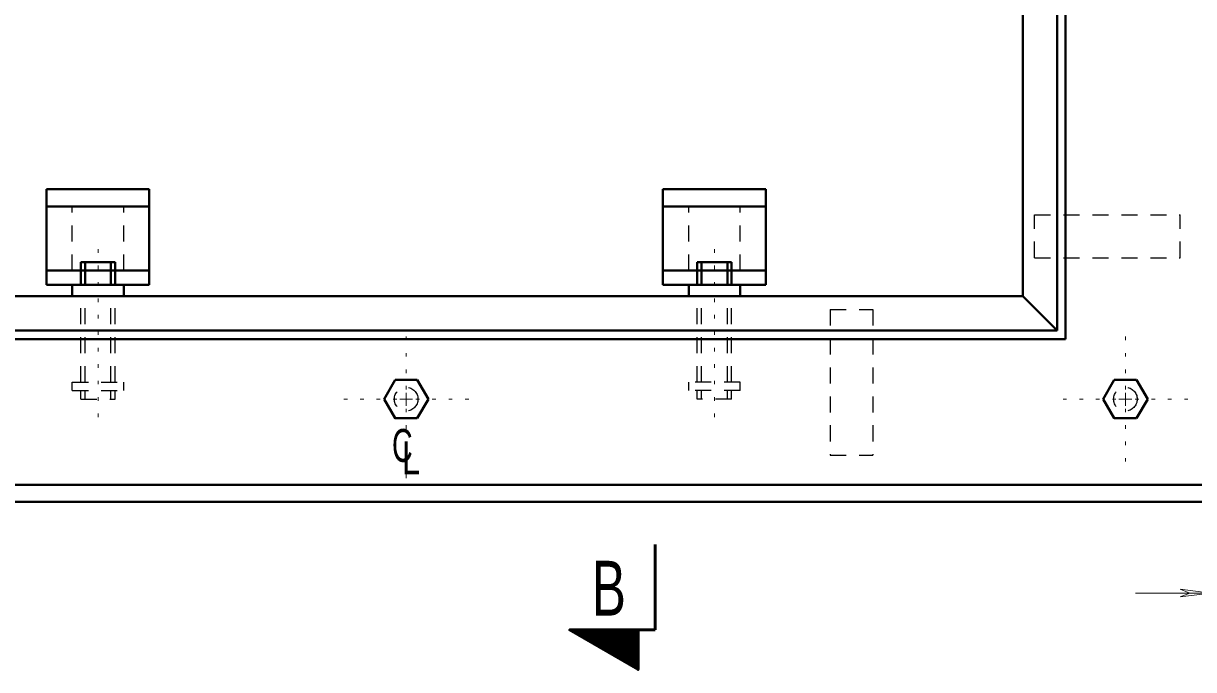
# Model space of a CAD drawing. Extents: x 312583 to 312853, y 144419 to 144586.
# Drawn here: x 312733.29 to 312766.04, y 144537.22 to 144555.29 of the extents above; entities that cross this region are included whole.
import ezdxf
from ezdxf.enums import TextEntityAlignment as Align

# ---------------------------------------------------------------- set-up
doc = ezdxf.new("R2010")
doc.units = 0
doc.header["$LTSCALE"] = 0.3
doc.linetypes.add('DOTTED', pattern=[1.5, 0.3, -1.2])
doc.linetypes.add('SHORT_DASHED', pattern=[2.7, 1.5, -1.2])
doc.layers.add('1', color=7, linetype='Continuous', lineweight=40)
doc.layers.add('2', color=7, linetype='Continuous', lineweight=13)

msp = doc.modelspace()

# ---------------------------------------------------------------- linework, layer by layer
at = {"layer": '1'}
for p, q in [((312761.2554, 144556.2456), (312761.2554, 144547.6589)), ((312733.939, 144550.6566), (312736.814, 144550.6566)), ((312733.939, 144547.9809), (312733.939, 144550.6566)), ((312736.814, 144547.9809), (312736.814, 144550.6566)), ((312754.064, 144550.6566), (312751.189, 144550.6566)), ((312751.189, 144547.9809), (312751.189, 144550.6566)), ((312754.064, 144547.9809), (312754.064, 144550.6566)), ((312733.939, 144550.1736), (312736.814, 144550.1736)), ((312754.064, 144550.1736), (312751.189, 144550.1736)), ((312733.939, 144548.3796), (312736.814, 144548.3796)), ((312734.8974, 144548.6172), (312735.8557, 144548.6172)), ((312734.8974, 144548.6172), (312734.8974, 144547.9809)), ((312735.02, 144548.6172), (312735.02, 144547.9809)), ((312735.7407, 144548.6172), (312735.7407, 144547.9809)), ((312735.8557, 144548.6172), (312735.8557, 144547.9809)), ((312754.064, 144548.3796), (312751.189, 144548.3796)), ((312753.1057, 144548.6172), (312752.1474, 144548.6172)), ((312752.1474, 144548.6172), (312752.1474, 144547.9809)), ((312752.27, 144548.6172), (312752.27, 144547.9809)), ((312752.9907, 144548.6172), (312752.9907, 144547.9809)), ((312753.1057, 144548.6172), (312753.1057, 144547.9809)), ((312733.939, 144547.9809), (312736.814, 144547.9809)), ((312734.6597, 144547.9809), (312734.6597, 144547.6589)), ((312736.101, 144547.9809), (312736.101, 144547.6589)), ((312754.064, 144547.9809), (312751.189, 144547.9809)), ((312751.9097, 144547.9809), (312751.9097, 144547.6589)), ((312753.351, 144547.9809), (312753.351, 144547.6589)), ((312761.2554, 144547.6589), (312762.2137, 144546.7006)), ((312725.5594, 144546.4629), (312762.4514, 144546.4629)), ((312725.797, 144546.7006), (312762.2137, 144546.7006)), ((312743.691, 144545.3206), (312743.3844, 144544.7839)), ((312744.312, 144545.3206), (312743.691, 144545.3206)), ((312744.6264, 144544.7839), (312744.312, 144545.3206)), ((312763.816, 144545.3206), (312763.5094, 144544.7839)), ((312764.437, 144545.3206), (312763.816, 144545.3206)), ((312764.7514, 144544.7839), (312764.437, 144545.3206)), ((312744.6264, 144544.7839), (312744.312, 144544.2472)), ((312764.7514, 144544.7839), (312764.437, 144544.2472)), ((312721.4807, 144542.3842), (312766.5224, 144542.3842)), ((312721.0054, 144541.9089), (312767.0054, 144541.9089))]:
    msp.add_line(p, q, dxfattribs=at)
at = {"layer": '1', "linetype": 'SHORT_DASHED', "lineweight": 25}
for p, q in [((312734.6597, 144548.3796), (312734.6597, 144550.1736)), ((312736.101, 144548.3796), (312736.101, 144550.1736)), ((312751.9097, 144548.3796), (312751.9097, 144550.1736)), ((312753.351, 144548.3796), (312753.351, 144550.1736)), ((312761.585, 144548.7399), (312761.585, 144549.9359)), ((312761.585, 144549.9359), (312765.656, 144549.9359)), ((312765.656, 144548.7399), (312765.656, 144549.9359)), ((312761.585, 144548.7399), (312765.656, 144548.7399)), ((312734.8974, 144545.2592), (312734.8974, 144547.6589)), ((312735.02, 144545.2592), (312735.02, 144547.6589)), ((312735.7407, 144545.2592), (312735.7407, 144547.6589)), ((312735.8557, 144545.2592), (312735.8557, 144547.6589)), ((312752.1474, 144545.2592), (312752.1474, 144547.6589)), ((312752.27, 144545.2592), (312752.27, 144547.6589)), ((312752.9907, 144545.2592), (312752.9907, 144547.6589)), ((312753.1057, 144545.2592), (312753.1057, 144547.6589)), ((312755.8657, 144547.2909), (312757.0617, 144547.2909)), ((312755.8657, 144547.2909), (312755.8657, 144543.2199)), ((312757.0617, 144547.2909), (312757.0617, 144543.2199)), ((312734.6597, 144545.2592), (312736.101, 144545.2592)), ((312734.6597, 144545.0216), (312734.6597, 144545.2592)), ((312736.101, 144545.0216), (312736.101, 144545.2592)), ((312753.351, 144545.2592), (312751.9097, 144545.2592)), ((312751.9097, 144545.0216), (312751.9097, 144545.2592)), ((312753.351, 144545.0216), (312753.351, 144545.2592)), ((312734.6597, 144545.0216), (312736.101, 144545.0216)), ((312734.8974, 144544.7839), (312734.8974, 144545.0216)), ((312734.8974, 144544.7839), (312735.8557, 144544.7839)), ((312735.02, 144544.7839), (312735.02, 144545.0216)), ((312735.7407, 144544.7839), (312735.7407, 144545.0216)), ((312735.8557, 144544.7839), (312735.8557, 144545.0216)), ((312753.351, 144545.0216), (312751.9097, 144545.0216)), ((312752.1474, 144544.7839), (312752.1474, 144545.0216)), ((312753.1057, 144544.7839), (312752.1474, 144544.7839)), ((312752.27, 144544.7839), (312752.27, 144545.0216)), ((312752.9907, 144544.7839), (312752.9907, 144545.0216)), ((312753.1057, 144544.7839), (312753.1057, 144545.0216)), ((312755.8657, 144543.2199), (312757.0617, 144543.2199))]:
    msp.add_line(p, q, dxfattribs=at)
at = {"layer": '1', "linetype": 'DOTTED', "lineweight": 13}
for p, q in [((312735.3804, 144544.2779), (312735.3804, 144549.0159)), ((312752.6304, 144544.2779), (312752.6304, 144549.0159))]:
    msp.add_line(p, q, dxfattribs=at)
at = {"layer": '1', "lineweight": 53}
for p in [(312750.9667, 144540.7206), (312750.4914, 144538.3286)]:
    msp.add_line(p, (312750.9667, 144538.3286), dxfattribs=at)
at = {"layer": '1', "lineweight": 35}
for p, q in [((312748.59, 144538.3286), (312748.59, 144538.3132)), ((312748.6207, 144538.3286), (312748.613, 144538.3056)), ((312748.6514, 144538.3286), (312748.6284, 144538.2902)), ((312748.6744, 144538.3286), (312748.6514, 144538.2826)), ((312748.705, 144538.3286), (312748.6744, 144538.2672)), ((312748.728, 144538.3286), (312748.6897, 144538.2596)), ((312748.7587, 144538.3286), (312748.7127, 144538.2442)), ((312748.7894, 144538.3286), (312748.7357, 144538.2366)), ((312748.82, 144538.3286), (312748.751, 144538.2212)), ((312748.843, 144538.3286), (312748.774, 144538.2136)), ((312748.866, 144538.3286), (312748.797, 144538.1982)), ((312748.8967, 144538.3286), (312748.82, 144538.1906)), ((312748.9197, 144538.3286), (312748.8354, 144538.1752)), ((312748.9504, 144538.3286), (312748.8584, 144538.1599)), ((312748.981, 144538.3286), (312748.8814, 144538.1522)), ((312749.0117, 144538.3286), (312748.8967, 144538.1369)), ((312749.0347, 144538.3286), (312748.9197, 144538.1216)), ((312749.0654, 144538.3286), (312748.9427, 144538.1139)), ((312749.0884, 144538.3286), (312748.958, 144538.0986)), ((312749.119, 144538.3286), (312748.981, 144538.0909)), ((312749.1497, 144538.3286), (312749.004, 144538.0756)), ((312749.1727, 144538.3286), (312749.0194, 144538.0679)), ((312749.2034, 144538.3286), (312749.05, 144538.0526)), ((312749.2264, 144538.3286), (312749.0654, 144538.0449)), ((312749.257, 144538.3286), (312749.0884, 144538.0296)), ((312749.2877, 144538.3286), (312749.1114, 144538.0219)), ((312749.3107, 144538.3286), (312749.1267, 144538.0066)), ((312749.3414, 144538.3286), (312749.1497, 144537.9989)), ((312749.3644, 144538.3286), (312749.1727, 144537.9836)), ((312749.395, 144538.3286), (312749.188, 144537.9682)), ((312749.418, 144538.3286), (312749.211, 144537.9606)), ((312749.4487, 144538.3286), (312749.234, 144537.9452)), ((312749.4794, 144538.3286), (312749.2494, 144537.9299)), ((312749.51, 144538.3286), (312749.2724, 144537.9222)), ((312749.533, 144538.3286), (312749.2954, 144537.9069)), ((312749.556, 144538.3286), (312749.3184, 144537.8992)), ((312749.5867, 144538.3286), (312749.3337, 144537.8839)), ((312749.6174, 144538.3286), (312749.3567, 144537.8762)), ((312749.6404, 144538.3286), (312749.3797, 144537.8609)), ((312749.671, 144538.3286), (312749.395, 144537.8532)), ((312749.7017, 144538.3286), (312749.418, 144537.8379)), ((312749.7247, 144538.3286), (312749.441, 144537.8302)), ((312749.7554, 144538.3286), (312749.4564, 144537.8149)), ((312749.786, 144538.3286), (312749.4794, 144537.8072)), ((312749.809, 144538.3286), (312749.5024, 144537.7919)), ((312749.8397, 144538.3209), (312749.5177, 144537.7766)), ((312749.8627, 144538.3286), (312749.5484, 144537.7689)), ((312749.8934, 144538.3286), (312749.5637, 144537.7536)), ((312749.9164, 144538.3286), (312749.5867, 144537.7459)), ((312749.947, 144538.3286), (312749.6097, 144537.7306)), ((312749.9777, 144538.3286), (312749.625, 144537.7229)), ((312750.0084, 144538.3286), (312749.648, 144537.7076)), ((312750.0314, 144538.3286), (312749.671, 144537.6999)), ((312750.0544, 144538.3286), (312749.6864, 144537.6846)), ((312750.085, 144538.3209), (312749.7094, 144537.6769)), ((312750.1157, 144538.3286), (312749.7324, 144537.6616)), ((312750.1387, 144538.3286), (312749.7477, 144537.6539)), ((312750.1694, 144538.3286), (312749.7707, 144537.6386)), ((312750.2, 144538.3286), (312749.7937, 144537.6232)), ((312750.223, 144538.3286), (312749.8167, 144537.6156)), ((312750.2537, 144538.3286), (312749.832, 144537.6002)), ((312750.2844, 144538.3286), (312749.855, 144537.5849)), ((312750.3074, 144538.3209), (312749.878, 144537.5772)), ((312750.338, 144538.3209), (312749.8934, 144537.5619)), ((312750.361, 144538.3286), (312749.9164, 144537.5542)), ((312750.3917, 144538.3286), (312749.9394, 144537.5389)), ((312750.4147, 144538.3286), (312749.9547, 144537.5312)), ((312750.4454, 144538.3286), (312749.9777, 144537.5159)), ((312750.476, 144538.3286), (312750.0007, 144537.5082)), ((312750.4914, 144538.3056), (312750.016, 144537.4929)), ((312750.4914, 144538.2519), (312750.0467, 144537.4852)), ((312750.4914, 144538.2136), (312750.062, 144537.4699)), ((312750.4914, 144538.1599), (312750.085, 144537.4622)), ((312750.4914, 144538.1139), (312750.108, 144537.4469)), ((312750.4914, 144538.0679), (312750.1234, 144537.4316)), ((312750.4914, 144538.0219), (312750.1464, 144537.4239)), ((312750.4914, 144537.9682), (312750.1694, 144537.4086)), ((312750.4914, 144537.9222), (312750.1847, 144537.3932)), ((312750.4914, 144537.8762), (312750.2077, 144537.3856)), ((312750.4914, 144537.8226), (312750.223, 144537.3702)), ((312750.4914, 144537.7766), (312750.246, 144537.3626)), ((312750.4914, 144537.7306), (312750.269, 144537.3472)), ((312750.4914, 144537.6769), (312750.2844, 144537.3396)), ((312750.4914, 144537.6309), (312750.315, 144537.3242)), ((312750.4914, 144537.5849), (312750.3304, 144537.3166)), ((312750.4914, 144537.5389), (312750.3534, 144537.3012)), ((312750.4914, 144537.4852), (312750.3764, 144537.2936)), ((312750.4914, 144537.4469), (312750.3917, 144537.2782)), ((312750.4914, 144537.3932), (312750.4147, 144537.2706)), ((312750.4914, 144537.3472), (312750.4377, 144537.2552)), ((312750.4914, 144537.2936), (312750.453, 144537.2399)), ((312750.4914, 144537.2476), (312750.476, 144537.2322))]:
    msp.add_line(p, q, dxfattribs=at)
at = {"layer": '1'}
for points in [[(312725.5594, 144566.1049), (312762.4514, 144566.1049), (312762.4514, 144546.4629)], [(312725.797, 144565.8672), (312762.2137, 144565.8672), (312762.2137, 144546.7006)], [(312726.7554, 144564.9089), (312726.7554, 144547.6589), (312761.2554, 144547.6589)], [(312744.312, 144544.2472), (312743.691, 144544.2472), (312743.3844, 144544.7839)], [(312764.437, 144544.2472), (312763.816, 144544.2472), (312763.5094, 144544.7839)]]:
    msp.add_lwpolyline(points, dxfattribs=at)
at = {"layer": '1', "lineweight": 53}
msp.add_lwpolyline([(312750.4914, 144538.3286), (312750.4914, 144537.2169), (312748.5747, 144538.3286)], close=True, dxfattribs=at)
at = {"layer": '1', "linetype": 'SHORT_DASHED', "lineweight": 25}
for centre in [(312744.0035, 144544.7829), (312764.1285, 144544.7829)]:
    msp.add_circle(centre, 0.3301, dxfattribs=at)
at = {"layer": '2', "linetype": 'DOTTED'}
for p, q in [((312744.0054, 144545.0522), (312744.0054, 144546.8539)), ((312764.1304, 144545.0522), (312764.1304, 144546.8539)), ((312743.737, 144544.7839), (312741.9354, 144544.7839)), ((312744.2737, 144544.7839), (312746.0677, 144544.7839)), ((312763.862, 144544.7839), (312762.0604, 144544.7839)), ((312764.3987, 144544.7839), (312766.1927, 144544.7839)), ((312744.0054, 144544.5156), (312744.0054, 144542.3382)), ((312764.1304, 144544.5156), (312764.1304, 144542.7139))]:
    msp.add_line(p, q, dxfattribs=at)
at = {"layer": '2'}
for p, q in [((312744.0054, 144544.7839), (312743.8214, 144544.7839)), ((312744.0054, 144544.7839), (312744.0054, 144544.9602)), ((312744.0054, 144544.7839), (312744.1817, 144544.7839)), ((312744.0054, 144544.7839), (312744.0054, 144544.5999)), ((312764.1304, 144544.7839), (312763.9464, 144544.7839)), ((312764.1304, 144544.7839), (312764.1304, 144544.9602)), ((312764.1304, 144544.7839), (312764.3067, 144544.7839)), ((312764.1304, 144544.7839), (312764.1304, 144544.5999)), ((312764.414, 144539.3559), (312766.5224, 144539.3559)), ((312765.656, 144539.4632), (312765.932, 144539.3559)), ((312766.5224, 144539.3559), (312765.656, 144539.4632)), ((312765.656, 144539.2486), (312765.932, 144539.3559)), ((312766.5224, 144539.3559), (312765.656, 144539.2486))]:
    msp.add_line(p, q, dxfattribs=at)

# ---------------------------------------------------------------- texts
at = {"layer": '1', "width": 0.7}
msp.add_text('B', height=1.533, dxfattribs=at).set_placement((312749.6749, 144538.7272), align=Align.CENTER)
at = {"layer": '2'}
for s, width, p in [('C', 0.65, (312743.6067, 144543.0282)), ('L', 0.75, (312743.8827, 144542.6832))]:
    msp.add_text(s, height=0.92, dxfattribs=dict(at, width=width)).set_placement(p)

doc.saveas('drawing.dxf')
